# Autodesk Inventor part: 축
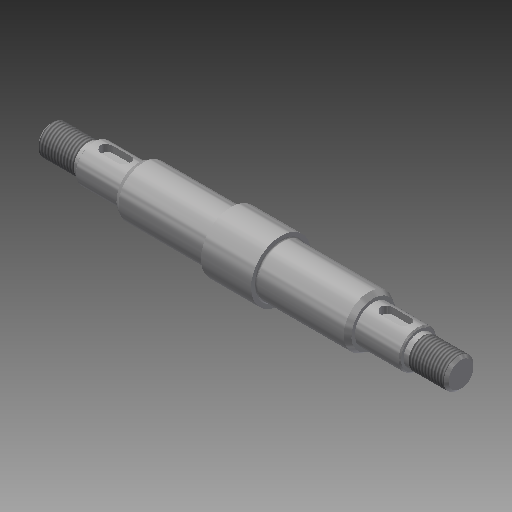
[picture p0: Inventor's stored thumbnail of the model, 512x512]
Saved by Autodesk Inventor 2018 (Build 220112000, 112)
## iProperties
Created: 2018-11
Part Number: 축
Material: 강철, 연강
Document SubType Name: Modeling
Designer: mduedu
Density: 1 g/cm^3
Appearance: 강철
Author: mduedu
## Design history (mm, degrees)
sketch "스케치1"
  geometry: L1 (-10, 0)-(10, 0); L2 (10, 0)-(10, 12); L3 (10, 12)-(-10, 12); L4 (-10, 12)-(-10, 0); L5 (-10, 0)-(-65, 0); L6 (-65, 0)-(-65, 7.5); L7 (-65, 7.5)-(-47, 7.5); L8 (-10, 7.5)-(-10, 0); L9 (-65, 0)-(-82, 0); L10 (-82, 0)-(-82, 6); L11 (-82, 6)-(-65, 6); L12 (-65, 6)-(-65, 0); L13 (0, 0)-(0, 12); L14 (10, 0)-(65, 0); L15 (65, 0)-(65, 7.5); L16 (65, 7.5)-(47, 7.5); L17 (10, 7.5)-(10, 0); L18 (65, 0)-(82, 0); L19 (82, 0)-(82, 6); L20 (82, 6)-(65, 6); L21 (65, 6)-(65, 0); L22 (-47, 7.5)-(-47, 8.85); L23 (-45.008, 10)-(-10, 10); L24 (10, 10)-(45.008, 10); L25 (47, 8.85)-(47, 7.5); L26 (-47, 8.85)-(-45.008, 10); L27 (47, 8.85)-(45.008, 10); 1 further point
  constraints: 54 end point, 9 parallel, 6 symmetric about line, 4 horizontal, 4 perpendicular, 2 midpoint, 2 point on line, 1 coincident
  dimensions: "d0" = 24 diameter of L3 L1; "d2" = 15 diameter of L7 L5; "d3" = 12 diameter of L11 L9; "d4" = 20 distance of L2.end L3.end; "d5" = 55 distance of L6.end L8.start; "d6" = 164 distance between parallel lines of L19 L10; "d24" = 20 diameter of L23 L5; "d25" = 18 distance of L6.end L7.end; "d26" = 18 distance of L15.end L16.end; "d27" = 20 diameter of L24 L14; "d28" = 55 distance between parallel lines of L15 L2; "d29" = 30 deg angle of L23 L26; "d30" = 17.7 diameter of L22.end L5; "d31" = 30 deg angle of L24 L27; "d32" = 17.7 diameter of L25.start L14
revolve "회전1" sketch "스케치1" stored, may be unused: angle "d7" = 90 deg
fillet "모깎기1" dims "d8" = 0.6
node "작업 평면1"
sketch "스케치2" dims "d11" = 12
  geometry: L1 (-3.5, 2.5)-(3.5, 2.5); L2 (3.5, 2.5)-(3.5, -2.5); L3 (3.5, -2.5)-(-3.5, -2.5); L4 (-3.5, -2.5)-(-3.5, 2.5); L5 (9, 7.5)-(9, -7.5) reference; 3 further points
  constraints: 8 end point, 2 midpoint, 2 parallel, 2 vertical alignment, 1 horizontal, 1 horizontal alignment, 1 perpendicular, 4 other
  dimensions: "d9" = 3 dimension on L5; "d10" = 5 distance between parallel lines of L3 L1
extrude "돌출1" cut sketch "스케치2" distance "d12" = 3; taper "d13" = 0 deg
chamfer "모따기1" distance "d14" = 0.5; stored, may be unused: second distance "d15" = 2, angle "d16" = 45 deg
feature "스레드1" dims "d17" = 15, "d18" = 0
feature "스레드2" dims "d19" = 15, "d20" = 0
chamfer "모따기2" distance "d21" = 1; stored, may be unused: second distance "d22" = 2, angle "d23" = 45 deg
node "솔리드1"
mirror "대칭1"
